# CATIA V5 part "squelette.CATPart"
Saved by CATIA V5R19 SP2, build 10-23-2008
Part number: squelette
Publications: "Plan.1", "Plan.2", "Plan.3", "Plan.4", "Plan.5", "Point.1", "Point.9", "Point.8", "Point.7", "Point.6", "Plan.7", "Point.10", "Droite.4", "Point.11", "Point.12", "Droite.5", "Point.13"
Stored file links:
  E:\IAO_2010\iao\IAO_MMS_Groupe2\IAO_MMS_Groupe2\OK\fvigouroux\vigouroux\vigouroux\squelette.CATPart

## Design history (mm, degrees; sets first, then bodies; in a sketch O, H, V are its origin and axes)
Set1
  Plane1: type Offset, RefPlane yz-plane, Offset 0
  Plane2: type Offset, RefPlane Plane1, Offset 15, reversed
  Plane3: type Offset, RefPlane Plane1, Offset 55, reversed
  Plane4: type Offset, RefPlane Plane1, Offset 60, reversed
  Plane5: type Offset, RefPlane Plane1, Offset 120, reversed
  Point1: (0, 0, 0)
  Point2: type OnPlane, Support Plane2, H 0, V 0, Direction (0, 1, 0)
  Point3: type OnPlane, Support Plane3, H 0, V 0, Direction (0, 1, 0)
  Point4: type OnPlane, Support Plane4, H 10, V 0, Direction (0, 1, 0)
  Point5: type OnPlane, Support Plane5, H 10, V 0, Direction (0, 1, 0)
  Plane6: type Offset, RefPlane Plane1, Offset 73, reversed
  Point6: type OnPlane, Support Plane6, H 10, V 0, Direction (0, 1, 0)
  Line1: type PtPt, FirstPoint Point4, SecondPoint Point6
  Point7: type OnPlane, Support Plane3, H -10, V 0, Direction (0, 1, 0)
  Point8: type OnPlane, Support Plane4, H -10, V 0, Direction (0, 1, 0)
  Line2: type PtPt, FirstPoint Point7, SecondPoint Point8
  Point9: type OnPlane, Support Plane3, H 10, V 0, Direction (0, 1, 0)
Body1 (main body)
